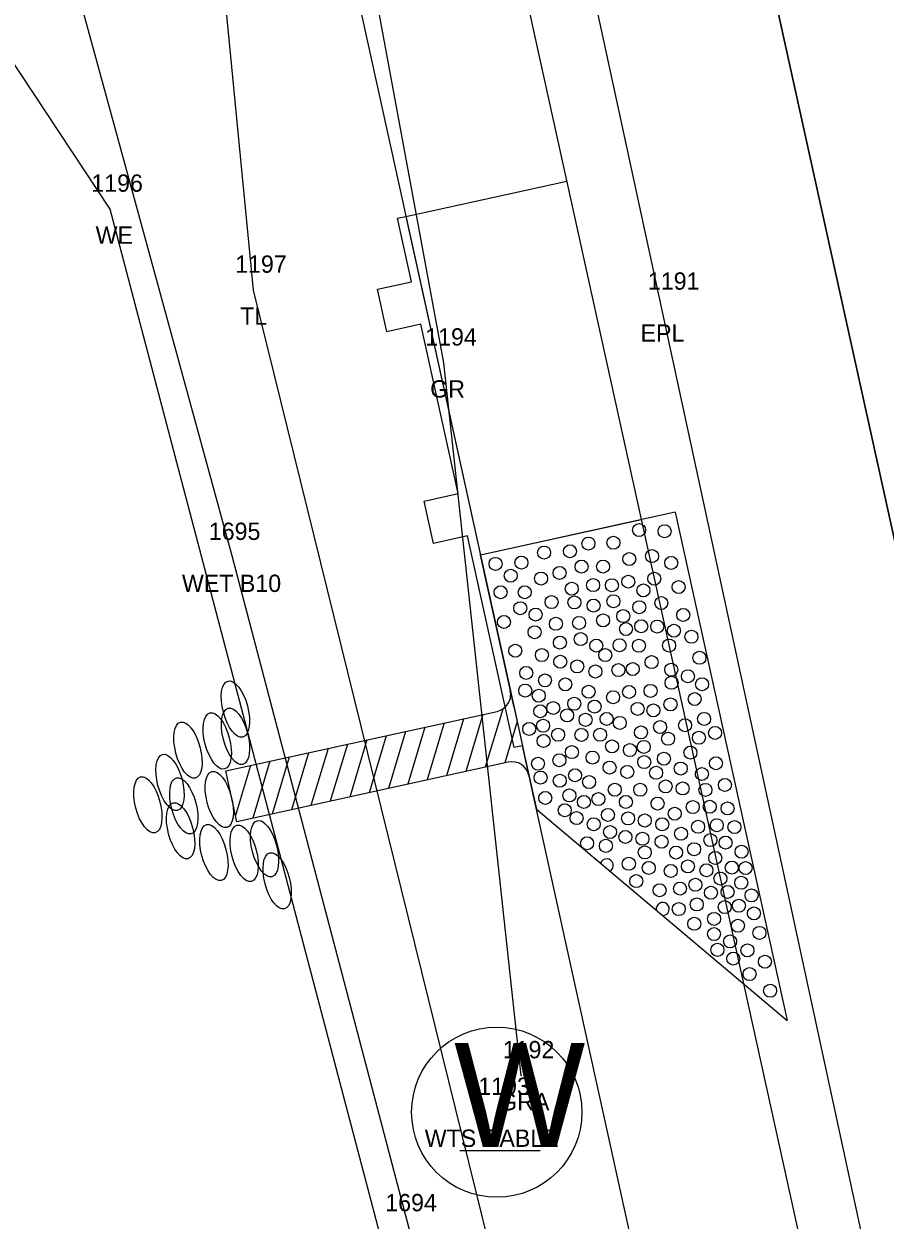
# Model space of a CAD drawing. Extents: x 2521558 to 2524785, y 882711 to 887632.
# Drawn here: x 2523758.7 to 2523808.4, y 884993.3 to 885062.2 of the extents above; entities that cross this region are included whole.
import ezdxf

# ---------------------------------------------------------------- set-up
doc = ezdxf.new("R2010")
doc.units = 0
for name, color, linetype in [('RD_EV_JurisArea', 7, 'Continuous'), ('RD_EX_GuardRail', 7, 'Continuous'), ('RD_EX_GuardRail_txCode', 7, 'Continuous'), ('RD_EX_H2O', 7, 'Continuous'), ('RD_EX_H2O_txCode', 7, 'Continuous'), ('RD_EX_H2O_WetLd_txCode', 7, 'Continuous'), ('RD_EX_Road', 7, 'Continuous'), ('RD_EX_Road_txCode', 7, 'Continuous'), ('RD_EX_UT', 7, 'Continuous'), ('RD_EX_UT_txCode', 7, 'Continuous'), ('RD_EX_VEG', 7, 'Continuous'), ('RD_EX_VEG_txCode', 7, 'Continuous'), ('RD_HC_Cl', 7, 'Continuous'), ('RD_PD_Bridge', 7, 'Continuous'), ('RD_PD_Final_TrvlWay', 7, 'Continuous'), ('RD_PD_GR', 7, 'Continuous'), ('RD_PD_PaveShd', 7, 'Continuous'), ('RD_PD_SuperShp1', 7, 'Continuous'), ('RD_SMD_Locator', 7, 'Continuous')]:
    doc.layers.add(name, color=color, linetype=linetype)

# ---------------------------------------------------------------- blocks, each defined once
blk = doc.blocks.new('TBC1')
at = {"layer": 'RD_PD_GR'}
blk.add_lwpolyline([(12.5, 2.5), (15, 2.5), (15, 0.492), (25, 0.492), (25, 2.5), (27.5, 2.5), (27.5, 0.492), (31.25, 0.492), (31.25, 0), (0, 0), (0, 0.492), (12.5, 0.492)], close=True, dxfattribs=at)

msp = doc.modelspace()

# ---------------------------------------------------------------- linework, layer by layer
at = {"layer": 'RD_EV_JurisArea'}
msp.add_lwpolyline([(2523827.748, 884469.643), (2523867.429, 884517.673), (2523885.95, 884534.838), (2523882.771, 884582.718), (2523847.739, 884736.424), (2523822.93, 884833.786), (2523804.257, 884914.891), (2523780.91, 884992.763), (2523770.735, 885031.476), (2523760.496, 885068.896)], dxfattribs=at)
at = {"layer": 'RD_EX_GuardRail'}
msp.add_lwpolyline([(2523787.377, 885001.584), (2523782.908, 885042.685), (2523776.151, 885079.302)], dxfattribs=at)
at = {"layer": 'RD_EX_H2O'}
msp.add_lwpolyline([(2523792.732, 884941.121), (2523763.674, 885051.555), (2523756.264, 885062.719), (2523770.471, 885094.548), (2523817.567, 885105.706), (2523827.825, 885105.996)], dxfattribs=at)
at = {"layer": 'RD_EX_Road'}
for p, q in [((2523795.465, 885045.906), (2523788.047, 885080.306)), ((2523816.996, 884946.299), (2523795.465, 885045.906))]:
    msp.add_line(p, q, dxfattribs=at)
at = {"layer": 'RD_EX_UT'}
msp.add_line((2523783.84, 884997.269), (2523788.469, 884997.269), dxfattribs=at)
msp.add_circle((2523785.968, 884999.477), 4.908, dxfattribs=at)
at = {"layer": 'RD_EX_VEG'}
msp.add_lwpolyline([(2523800.231, 884418.22), (2523892.245, 884498.974), (2523844.575, 884752.813), (2523771.945, 885046.883), (2523769.056, 885076.621)], dxfattribs=at)
at = {"layer": 'RD_HC_Cl'}
msp.add_line((2523641.165, 885794.201), (2524197.759, 883266.557), dxfattribs=at)
at = {"layer": 'RD_PD_Bridge'}
msp.add_line((2523794.308, 885033.639), (2523785.03, 885031.596), dxfattribs=at)
for points in [[(2523748.471, 885197.618), (2523785.03, 885031.596)], [(2523780.729, 885051.128), (2523790.007, 885053.171)]]:
    msp.add_lwpolyline(points, dxfattribs=at)
at = {"layer": 'RD_PD_Final_TrvlWay'}
msp.add_line((2523696.998, 885475.549), (2524012.047, 884044.826), dxfattribs=at)
at = {"layer": 'RD_PD_GR'}
msp.add_line((2523854.115, 884717.862), (2523787.449, 885020.609), dxfattribs=at)
at = {"layer": 'RD_PD_PaveShd'}
for p, q in [((2523796.261, 885034.069), (2523785.03, 885031.596)), ((2523796.261, 885034.069), (2523802.712, 885004.771)), ((2523786.965, 885022.806), (2523785.03, 885031.596)), ((2523785.03, 885031.596), (2523786.965, 885022.806)), ((2523770.341, 885019.155), (2523785.988, 885022.592)), ((2523786.312, 885022.726), (2523785.308, 885019.371)), ((2523786.965, 885022.806), (2523787.611, 885019.877)), ((2523782.94, 885021.922), (2523781.956, 885018.635)), ((2523782.94, 885021.922), (2523781.956, 885018.635)), ((2523784.058, 885022.168), (2523783.074, 885018.88)), ((2523784.058, 885022.168), (2523783.074, 885018.88)), ((2523785.175, 885022.413), (2523784.191, 885019.125)), ((2523785.175, 885022.413), (2523784.191, 885019.125)), ((2523787.141, 885022.007), (2523786.426, 885019.616)), ((2523787.179, 885021.836), (2523787.179, 885021.836)), ((2523779.589, 885021.186), (2523778.605, 885017.898)), ((2523779.589, 885021.186), (2523778.605, 885017.898)), ((2523780.706, 885021.431), (2523779.722, 885018.144)), ((2523780.706, 885021.431), (2523779.722, 885018.144)), ((2523781.823, 885021.677), (2523780.839, 885018.389)), ((2523781.823, 885021.677), (2523780.839, 885018.389)), ((2523776.237, 885020.45), (2523775.253, 885017.162)), ((2523776.237, 885020.45), (2523775.253, 885017.162)), ((2523777.354, 885020.695), (2523776.37, 885017.407)), ((2523777.354, 885020.695), (2523776.37, 885017.407)), ((2523778.471, 885020.941), (2523777.487, 885017.653)), ((2523778.471, 885020.941), (2523777.487, 885017.653)), ((2523774.002, 885019.959), (2523773.018, 885016.671)), ((2523774.002, 885019.959), (2523773.018, 885016.671)), ((2523775.119, 885020.204), (2523774.135, 885016.917)), ((2523775.119, 885020.204), (2523774.135, 885016.917)), ((2523787.611, 885019.877), (2523788.256, 885016.947)), ((2523770.984, 885016.224), (2523770.341, 885019.155)), ((2523770.984, 885016.224), (2523770.341, 885019.155)), ((2523771.768, 885019.468), (2523770.905, 885016.586)), ((2523771.768, 885019.468), (2523770.905, 885016.586)), ((2523786.634, 885019.662), (2523770.984, 885016.224)), ((2523772.885, 885019.713), (2523771.901, 885016.426)), ((2523772.885, 885019.713), (2523771.901, 885016.426)), ((2523788.256, 885016.947), (2523802.712, 885004.771))]:
    msp.add_line(p, q, dxfattribs=at)
for centre in [(2523794.177, 885033.047), (2523794.177, 885033.047), (2523795.645, 885032.98), (2523795.645, 885032.98), (2523790.191, 885031.82), (2523790.191, 885031.82), (2523791.255, 885032.267), (2523791.255, 885032.267), (2523792.695, 885032.312), (2523792.695, 885032.312), (2523785.901, 885031.098), (2523785.901, 885031.098), (2523787.391, 885031.169), (2523787.391, 885031.169), (2523787.391, 885031.169), (2523788.701, 885031.749), (2523788.701, 885031.749), (2523793.614, 885031.376), (2523793.614, 885031.376), (2523794.925, 885031.542), (2523794.925, 885031.542), (2523796.028, 885031.15), (2523796.028, 885031.15), (2523786.773, 885030.414), (2523789.59, 885030.574), (2523789.59, 885030.574), (2523790.857, 885030.939), (2523790.857, 885030.939), (2523792.098, 885030.94), (2523792.098, 885030.94), (2523788.522, 885030.252), (2523788.522, 885030.252), (2523791.529, 885029.869), (2523791.529, 885029.869), (2523792.61, 885029.863), (2523792.61, 885029.863), (2523793.554, 885030.07), (2523793.554, 885030.07), (2523795.053, 885030.242), (2523795.053, 885030.242), (2523796.459, 885029.76), (2523796.459, 885029.76), (2523786.194, 885029.459), (2523786.194, 885029.459), (2523787.581, 885029.458), (2523787.581, 885029.458), (2523790.297, 885029.666), (2523790.297, 885029.666), (2523794.424, 885029.569), (2523794.424, 885029.569), (2523787.326, 885028.541), (2523787.326, 885028.541), (2523789.128, 885028.892), (2523789.128, 885028.892), (2523790.445, 885028.871), (2523790.445, 885028.871), (2523791.55, 885028.688), (2523791.55, 885028.688), (2523792.699, 885028.941), (2523792.699, 885028.941), (2523794.188, 885028.599), (2523794.188, 885028.599), (2523795.46, 885028.839), (2523795.46, 885028.839), (2523786.385, 885027.748), (2523786.385, 885027.748), (2523788.21, 885028.175), (2523788.21, 885028.175), (2523789.378, 885027.639), (2523789.378, 885027.639), (2523790.717, 885027.693), (2523790.717, 885027.693), (2523792.104, 885027.837), (2523792.104, 885027.837), (2523793.26, 885028.082), (2523796.722, 885028.151), (2523796.722, 885028.151), (2523788.153, 885027.158), (2523788.153, 885027.158), (2523793.423, 885027.339), (2523793.423, 885027.339), (2523794.299, 885027.497), (2523794.299, 885027.497), (2523795.224, 885027.483), (2523795.224, 885027.483), (2523796.188, 885027.242), (2523796.188, 885027.242), (2523789.612, 885026.556), (2523789.612, 885026.556), (2523790.809, 885026.756), (2523790.809, 885026.756), (2523791.71, 885026.383), (2523791.71, 885026.383), (2523793.053, 885026.403), (2523793.053, 885026.403), (2523794.168, 885026.372), (2523794.168, 885026.372), (2523795.909, 885026.389), (2523795.909, 885026.389), (2523797.198, 885026.893), (2523797.198, 885026.893), (2523787.039, 885026.09), (2523787.039, 885026.09), (2523788.569, 885025.835), (2523788.569, 885025.835), (2523792.229, 885025.836), (2523792.229, 885025.836), (2523797.661, 885025.679), (2523797.661, 885025.679), (2523789.633, 885025.454), (2523789.633, 885025.454), (2523790.607, 885025.184), (2523790.607, 885025.184), (2523791.656, 885024.89), (2523791.656, 885024.89), (2523792.982, 885024.969), (2523792.982, 885024.969), (2523793.808, 885025.033), (2523793.808, 885025.033), (2523794.899, 885025.43), (2523794.899, 885025.43), (2523796.028, 885024.989), (2523796.028, 885024.989), (2523787.667, 885024.806), (2523787.667, 885024.806), (2523788.751, 885024.374), (2523788.751, 885024.374), (2523796.051, 885024.238), (2523796.051, 885024.238), (2523796.992, 885024.618), (2523796.992, 885024.618), (2523787.611, 885023.79), (2523787.611, 885023.79), (2523789.924, 885024.147), (2523789.924, 885024.147), (2523791.266, 885023.725), (2523791.266, 885023.725), (2523793.598, 885023.71), (2523793.598, 885023.71), (2523794.837, 885023.774), (2523794.837, 885023.774), (2523797.807, 885024.157), (2523788.393, 885023.493), (2523790.438, 885023.028), (2523790.438, 885023.028), (2523791.609, 885022.864), (2523791.609, 885022.864), (2523792.68, 885023.406), (2523792.68, 885023.406), (2523795.989, 885022.995), (2523795.989, 885022.995), (2523797.383, 885023.302), (2523797.383, 885023.302), (2523788.479, 885022.594), (2523788.479, 885022.594), (2523789.226, 885022.785), (2523789.226, 885022.785), (2523790.029, 885022.359), (2523790.029, 885022.359), (2523792.304, 885022.154), (2523792.304, 885022.154), (2523794.092, 885022.736), (2523794.092, 885022.736), (2523795.002, 885022.647), (2523795.002, 885022.647), (2523797.929, 885022.157), (2523797.929, 885022.157), (2523787.843, 885021.575), (2523787.843, 885021.575), (2523788.643, 885021.759), (2523788.643, 885021.759), (2523791.09, 885022.103), (2523791.09, 885022.103), (2523793.064, 885021.927), (2523793.064, 885021.927), (2523795.39, 885021.686), (2523795.39, 885021.686), (2523796.828, 885021.793), (2523796.828, 885021.793), (2523788.67, 885020.883), (2523788.67, 885020.883), (2523789.509, 885021.243), (2523789.509, 885021.243), (2523790.85, 885021.234), (2523790.85, 885021.234), (2523791.928, 885021.243), (2523791.928, 885021.243), (2523794.284, 885021.376), (2523794.284, 885021.376), (2523795.849, 885021.011), (2523795.849, 885021.011), (2523797.624, 885021.069), (2523797.624, 885021.069), (2523798.556, 885021.349), (2523798.556, 885021.349), (2523790.304, 885020.24), (2523790.304, 885020.24), (2523792.616, 885020.572), (2523792.616, 885020.572), (2523793.648, 885020.356), (2523793.648, 885020.356), (2523794.447, 885020.541), (2523794.447, 885020.541), (2523797.14, 885020.211), (2523797.14, 885020.211), (2523788.348, 885019.57), (2523788.348, 885019.57), (2523789.581, 885019.774), (2523789.581, 885019.774), (2523791.492, 885019.926), (2523791.492, 885019.926), (2523794.474, 885019.665), (2523794.474, 885019.665), (2523795.609, 885019.863), (2523795.609, 885019.863), (2523798.61, 885019.596), (2523798.61, 885019.596), (2523788.496, 885018.775), (2523788.496, 885018.775), (2523790.483, 885018.905), (2523790.483, 885018.905), (2523792.478, 885019.352), (2523792.478, 885019.352), (2523793.498, 885019.099), (2523793.498, 885019.099), (2523795.158, 885019.047), (2523795.158, 885019.047), (2523796.576, 885019.295), (2523796.576, 885019.295), (2523797.805, 885018.979), (2523797.805, 885018.979), (2523789.602, 885018.593), (2523789.602, 885018.593), (2523791.298, 885018.516), (2523791.298, 885018.516), (2523792.778, 885018.074), (2523792.778, 885018.074), (2523794.245, 885018.069), (2523794.245, 885018.069), (2523795.708, 885018.262), (2523795.708, 885018.262), (2523796.687, 885018.145), (2523796.687, 885018.145), (2523798.005, 885018.061), (2523798.005, 885018.061), (2523799.125, 885018.346), (2523799.125, 885018.346), (2523788.769, 885017.598), (2523788.769, 885017.598), (2523790.156, 885017.741), (2523790.156, 885017.741), (2523790.156, 885017.741), (2523790.995, 885017.367), (2523790.995, 885017.367), (2523791.829, 885017.53), (2523791.829, 885017.53), (2523793.414, 885017.367), (2523793.414, 885017.367), (2523789.892, 885016.887), (2523792.384, 885016.62), (2523792.384, 885016.62), (2523795.247, 885017.273), (2523795.247, 885017.273), (2523796.23, 885016.69), (2523796.23, 885016.69), (2523797.274, 885017.07), (2523797.274, 885017.07), (2523798.251, 885017.088), (2523798.251, 885017.088), (2523799.279, 885016.998), (2523799.279, 885016.998), (2523790.572, 885016.439), (2523790.572, 885016.439), (2523791.561, 885016.081), (2523791.561, 885016.081), (2523793.543, 885016.418), (2523793.543, 885016.418), (2523794.5, 885016.298), (2523794.5, 885016.298), (2523795.509, 885016.078), (2523795.509, 885016.078), (2523797.58, 885015.934), (2523797.58, 885015.934), (2523798.659, 885016.025), (2523798.659, 885016.025), (2523799.679, 885015.921), (2523799.679, 885015.921), (2523792.502, 885015.634), (2523792.502, 885015.634), (2523793.388, 885015.348), (2523793.388, 885015.348), (2523794.369, 885015.241), (2523794.369, 885015.241), (2523796.597, 885015.531), (2523796.597, 885015.531), (2523791.183, 885014.983), (2523792.263, 885014.837), (2523792.263, 885014.837), (2523795.477, 885015.075), (2523795.477, 885015.075), (2523797.351, 885014.644), (2523797.351, 885014.644), (2523798.288, 885015.167), (2523798.288, 885015.167), (2523799.166, 885015.023), (2523799.166, 885015.023), (2523794.506, 885014.456), (2523794.506, 885014.456), (2523796.308, 885014.448), (2523796.308, 885014.448), (2523798.57, 885014.138), (2523798.57, 885014.138), (2523800.085, 885014.5), (2523800.085, 885014.5), (2523793.586, 885013.8), (2523793.586, 885013.8), (2523794.734, 885013.56), (2523794.734, 885013.56), (2523796.006, 885013.387), (2523796.006, 885013.387), (2523796.992, 885013.653), (2523796.992, 885013.653), (2523798.062, 885013.427), (2523798.062, 885013.427), (2523799.526, 885013.58), (2523799.526, 885013.58), (2523800.322, 885013.555), (2523800.322, 885013.555), (2523794.015, 885012.8), (2523797.422, 885012.591), (2523797.422, 885012.591), (2523798.865, 885012.951), (2523798.865, 885012.951), (2523800.068, 885012.709), (2523800.068, 885012.709), (2523795.363, 885012.277), (2523795.363, 885012.277), (2523796.537, 885012.372), (2523796.537, 885012.372), (2523798.324, 885012.132), (2523798.324, 885012.132), (2523799.283, 885012.176), (2523799.283, 885012.176), (2523800.664, 885011.976), (2523800.664, 885011.976), (2523796.466, 885011.188), (2523796.466, 885011.188), (2523797.507, 885011.455), (2523797.507, 885011.455), (2523799.116, 885011.305), (2523799.116, 885011.305), (2523799.93, 885011.38), (2523799.93, 885011.38), (2523798.499, 885010.627), (2523798.499, 885010.627), (2523800.803, 885010.942), (2523800.803, 885010.942), (2523797.362, 885010.34), (2523797.362, 885010.34), (2523798.498, 885009.749), (2523799.88, 885010.226), (2523799.88, 885010.226), (2523801.117, 885009.82), (2523801.117, 885009.82), (2523799.421, 885009.323), (2523799.421, 885009.323), (2523798.698, 885008.84), (2523799.609, 885008.334), (2523799.609, 885008.334), (2523800.425, 885008.81), (2523800.425, 885008.81), (2523801.434, 885008.154), (2523801.434, 885008.154), (2523800.546, 885007.439), (2523800.546, 885007.439), (2523801.736, 885006.481), (2523801.736, 885006.481)]:
    msp.add_circle(centre, 0.375, dxfattribs=at)
for centre, radius, start, end in [((2523785.774, 885023.568), 1, 282.38886, 12.41848), ((2523786.849, 885018.685), 1, 12.41848, 102.38886), ((2523792.314, 885013.712), 0.375, 297.93937, 161.84996), ((2523795.544, 885011.201), 0.375, 266.75217, 193.03716)]:
    msp.add_arc(centre, radius, start, end, dxfattribs=at)
for centre in [(2523770.896, 885022.723), (2523770.896, 885022.723), (2523769.849, 885020.885), (2523769.849, 885020.885), (2523770.903, 885021.151), (2523770.903, 885021.151), (2523768.16, 885020.356), (2523768.16, 885020.356), (2523767.126, 885018.494), (2523767.126, 885018.494), (2523769.968, 885017.507), (2523769.968, 885017.507), (2523765.849, 885017.201), (2523765.849, 885017.201), (2523767.92, 885017.14), (2523767.92, 885017.14), (2523767.738, 885015.706), (2523767.738, 885015.706), (2523772.578, 885014.672), (2523769.657, 885014.45), (2523769.657, 885014.45), (2523771.402, 885014.404), (2523771.402, 885014.404), (2523773.306, 885012.822)]:
    msp.add_ellipse(centre, major_axis=(0.426, -1.616), ratio=0.429445, dxfattribs=at)
at = {"layer": 'RD_PD_SuperShp1'}
for p, q in [((2524025.719, 884047.837), (2523710.67, 885478.56)), ((2523710.67, 885478.56), (2524025.719, 884047.837)), ((2523696.998, 885475.549), (2524012.047, 884044.826))]:
    msp.add_line(p, q, dxfattribs=at)
at = {"layer": 'RD_SMD_Locator'}
for centre in [(2523763.674, 885051.555), (2523771.945, 885046.883), (2523795.465, 885045.906), (2523782.908, 885042.685), (2523770.735, 885031.476), (2523787.377, 885001.584)]:
    msp.add_circle(centre, 0.001, dxfattribs=at)

# ---------------------------------------------------------------- block references
at = {"layer": 'RD_PD_Bridge', "rotation": 102.41848259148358}
msp.add_blockref('TBC1', (2523787.449, 885020.609), dxfattribs=at)

# ---------------------------------------------------------------- texts
at = {"layer": 'RD_EX_GuardRail_txCode'}
for s, p in [('1194', (2523781.845, 885043.685)), ('GR', (2523782.129, 885040.685)), ('1192', (2523786.314, 885002.584)), ('GRA', (2523786.109, 884999.584))]:
    msp.add_text(s, height=1, dxfattribs=at).set_placement(p)
at = {"layer": 'RD_EX_H2O_txCode'}
for s, p in [('1196', (2523762.587, 885052.555)), ('WE', (2523762.835, 885049.555))]:
    msp.add_text(s, height=1, dxfattribs=at).set_placement(p)
at = {"layer": 'RD_EX_H2O_WetLd_txCode'}
for s, p in [('1695', (2523769.365, 885032.476)), ('WET B10', (2523767.813, 885029.476)), ('1694', (2523779.54, 884993.763))]:
    msp.add_text(s, height=1, dxfattribs=at).set_placement(p)
at = {"layer": 'RD_EX_Road_txCode'}
for s, p in [('1191', (2523794.686, 885046.906)), ('EPL', (2523794.261, 885043.906))]:
    msp.add_text(s, height=1, dxfattribs=at).set_placement(p)
at = {"layer": 'RD_EX_UT'}
msp.add_text('W', height=6, dxfattribs=at).set_placement((2523783.504, 884997.476))
at = {"layer": 'RD_EX_UT_txCode'}
for s, p in [('1193', (2523784.905, 885000.477)), ('WTS CABLE', (2523781.815, 884997.477))]:
    msp.add_text(s, height=1, dxfattribs=at).set_placement(p)
at = {"layer": 'RD_EX_VEG_txCode'}
for s, p in [('1197', (2523770.882, 885047.883)), ('TL', (2523771.173, 885044.883))]:
    msp.add_text(s, height=1, dxfattribs=at).set_placement(p)

doc.saveas('drawing.dxf')
